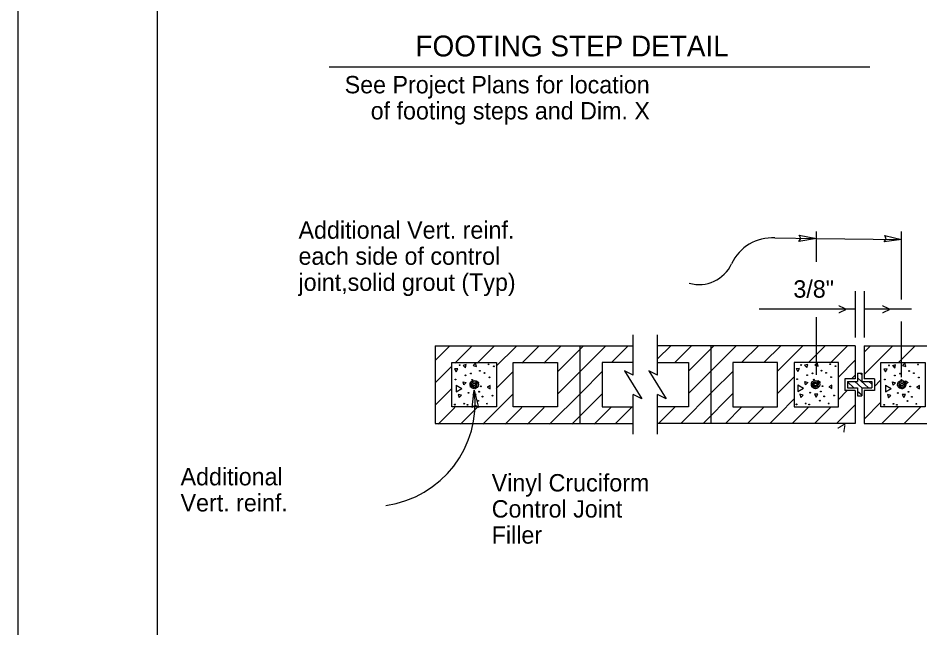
# Model space of a CAD drawing. Extents: x 0 to 2.83, y -0.03 to 1.83.
# Drawn here: x 0 to 0.675, y 0.861 to 1.317 of the extents above; entities that cross this region are included whole.
import ezdxf

# ---------------------------------------------------------------- set-up
doc = ezdxf.new("R2010")
doc.units = 0
for name, color, linetype in [('40', 7, 'Continuous'), ('50', 7, 'Continuous'), ('51', 7, 'Continuous'), ('52', 7, 'Continuous'), ('55', 7, 'Continuous'), ('57', 7, 'Continuous'), ('58', 7, 'Continuous'), ('63', 7, 'Continuous')]:
    doc.layers.add(name, color=color, linetype=linetype)

msp = doc.modelspace()

# ---------------------------------------------------------------- linework, layer by layer
at = {"layer": '40'}
for p, q in [((0.62848, 1.05162), (0.62848, 1.04547)), ((0.62848, 1.05162), (0.63155, 1.05162)), ((0.62848, 1.04833), (0.63661, 1.04084)), ((0.6303, 1.05162), (0.63155, 1.05046)), ((0.63155, 1.05162), (0.63155, 1.04547)), ((0.62095, 1.04547), (0.62095, 1.04084)), ((0.62095, 1.04547), (0.62848, 1.04547)), ((0.62095, 1.04514), (0.62563, 1.04084)), ((0.62095, 1.04084), (0.62848, 1.04084)), ((0.6263, 1.04547), (0.63155, 1.04064)), ((0.62848, 1.04084), (0.62848, 1.03469)), ((0.63155, 1.04547), (0.63908, 1.04547)), ((0.63155, 1.04084), (0.63155, 1.03469)), ((0.63155, 1.04084), (0.63908, 1.04084)), ((0.63699, 1.04547), (0.63908, 1.04355)), ((0.63908, 1.04547), (0.63908, 1.04084)), ((0.62848, 1.03822), (0.63155, 1.0354)), ((0.62848, 1.03469), (0.63155, 1.03469))]:
    msp.add_line(p, q, dxfattribs=at)
at = {"layer": '50'}
for p, q in [((0.59762, 1.13509), (0.59762, 1.15766)), ((0.66126, 1.10677), (0.66126, 1.15766)), ((0.59762, 1.05041), (0.59762, 1.09363)), ((0.66126, 1.04875), (0.66126, 1.09045)), ((0.31237, 1.07227), (0.31237, 1.01403)), ((0.31237, 1.07227), (0.46054, 1.07227)), ((0.42052, 1.07227), (0.42052, 1.01403)), ((0.62669, 1.07227), (0.4787, 1.07227)), ((0.51852, 1.07227), (0.51852, 1.01403)), ((0.62669, 1.07227), (0.62669, 1.0475)), ((0.63334, 1.07227), (0.7826, 1.07227)), ((0.63334, 1.07227), (0.63334, 1.0475)), ((0.61887, 1.0475), (0.61887, 1.03881)), ((0.62669, 1.0475), (0.61887, 1.0475)), ((0.64116, 1.0475), (0.63334, 1.0475)), ((0.64116, 1.0475), (0.64116, 1.03881)), ((0.62669, 1.03881), (0.61887, 1.03881)), ((0.62669, 1.03881), (0.62669, 1.01403)), ((0.64116, 1.03881), (0.63334, 1.03881)), ((0.63334, 1.03881), (0.63334, 1.01403)), ((0.31237, 1.01403), (0.46054, 1.01403)), ((0.62669, 1.01403), (0.4787, 1.01403)), ((0.63334, 1.01403), (0.7826, 1.01403))]:
    msp.add_line(p, q, dxfattribs=at)
for points in [[(0.32485, 1.02651), (0.32485, 1.0598), (0.35813, 1.0598), (0.35813, 1.02651)], [(0.37062, 1.02651), (0.37062, 1.0598), (0.4039, 1.0598), (0.4039, 1.02651)], [(0.56844, 1.02651), (0.56844, 1.0598), (0.53516, 1.0598), (0.53516, 1.02651)], [(0.61421, 1.02651), (0.61421, 1.0598), (0.58092, 1.0598), (0.58092, 1.02651)], [(0.64582, 1.02651), (0.64582, 1.0598), (0.67911, 1.0598), (0.67911, 1.02651)]]:
    msp.add_lwpolyline(points, close=True, dxfattribs=at)
for points in [[(0.46054, 1.0598), (0.43715, 1.0598), (0.43715, 1.02651), (0.46054, 1.02651)], [(0.4787, 1.0598), (0.50191, 1.0598), (0.50191, 1.02651), (0.4787, 1.02651)]]:
    msp.add_lwpolyline(points, dxfattribs=at)
for centre in [(0.33057, 1.05765), (0.34568, 1.05342), (0.35228, 1.05831), (0.35612, 1.05681), (0.58632, 1.0578), (0.60143, 1.05357), (0.60803, 1.05846), (0.61187, 1.05696), (0.65197, 1.05754), (0.66708, 1.05331), (0.67368, 1.0582), (0.32749, 1.04704), (0.33502, 1.05011), (0.33903, 1.05144), (0.33996, 1.04673), (0.34912, 1.05184), (0.35286, 1.04858), (0.58324, 1.04719), (0.59077, 1.05026), (0.59478, 1.05159), (0.59571, 1.04688), (0.60487, 1.05199), (0.60861, 1.04873), (0.64889, 1.04693), (0.65642, 1.05001), (0.66043, 1.05133), (0.66136, 1.04662), (0.67052, 1.05173), (0.67426, 1.04847), (0.33894, 1.04153), (0.34643, 1.04184), (0.59469, 1.04168), (0.60218, 1.04199), (0.66034, 1.04142), (0.66783, 1.04173), (0.33722, 1.037), (0.3452, 1.03783), (0.34775, 1.03418), (0.35511, 1.03488), (0.59297, 1.03715), (0.60095, 1.03798), (0.6035, 1.03433), (0.61086, 1.03503), (0.65862, 1.03689), (0.6666, 1.03772), (0.66915, 1.03407), (0.32705, 1.02819), (0.33388, 1.02889), (0.33643, 1.02806), (0.3444, 1.03101), (0.35105, 1.02889), (0.5828, 1.02834), (0.58963, 1.02904), (0.59218, 1.02821), (0.60015, 1.03116), (0.6068, 1.02904), (0.64845, 1.02808), (0.65528, 1.02878), (0.65783, 1.02795), (0.6658, 1.0309), (0.67245, 1.02878)]:
    msp.add_circle(centre, 0.000305, dxfattribs=at)
at = {"layer": '51'}
for p, q in [((0.32792, 1.04276), (0.32793, 1.0378)), ((0.32793, 1.04275), (0.33222, 1.04029)), ((0.32793, 1.0378), (0.33222, 1.04027)), ((0.34148, 1.04315), (0.34148, 1.04315)), ((0.34148, 1.04315), (0.34148, 1.04315)), ((0.58367, 1.04291), (0.58367, 1.03795)), ((0.58367, 1.0429), (0.58797, 1.04044)), ((0.58367, 1.03795), (0.58797, 1.04042)), ((0.59699, 1.0432), (0.59699, 1.0432)), ((0.59699, 1.0432), (0.59699, 1.0432)), ((0.64932, 1.04265), (0.64932, 1.03769)), ((0.64932, 1.04264), (0.65362, 1.04018)), ((0.64932, 1.03769), (0.65362, 1.04016)), ((0.66156, 1.04314), (0.66156, 1.04314)), ((0.66156, 1.04314), (0.66156, 1.04314))]:
    msp.add_line(p, q, dxfattribs=at)
for points in [[(0.34147, 1.04004), (0.3399, 1.04048), (0.33883, 1.04156), (0.3384, 1.04278), (0.33857, 1.04427), (0.33925, 1.04535), (0.34027, 1.04602), (0.34155, 1.04626), (0.34283, 1.04597), (0.34378, 1.04527), (0.34437, 1.04436), (0.34462, 1.04318), (0.34437, 1.04196), (0.3438, 1.04109), (0.34295, 1.04039), (0.34213, 1.0401), (0.34158, 1.04003), (0.34112, 1.0411), (0.34018, 1.04153), (0.33952, 1.04254), (0.33952, 1.04375), (0.3401, 1.04472), (0.34118, 1.04522), (0.34258, 1.04492), (0.3433, 1.04418), (0.34357, 1.04311), (0.34328, 1.04211), (0.34268, 1.04145), (0.34187, 1.04109), (0.34115, 1.04109), (0.34088, 1.04231), (0.3405, 1.04286), (0.34055, 1.04357), (0.34107, 1.04408), (0.34195, 1.04407), (0.34245, 1.04353), (0.34243, 1.04277), (0.3419, 1.04221), (0.34125, 1.04214), (0.34088, 1.04228)], [(0.59697, 1.04008), (0.59539, 1.04052), (0.59432, 1.0416), (0.59389, 1.04282), (0.59407, 1.04431), (0.59476, 1.04539), (0.59576, 1.04606), (0.59706, 1.0463), (0.59832, 1.04601), (0.59927, 1.04531), (0.59986, 1.0444), (0.60011, 1.04322), (0.59987, 1.042), (0.59929, 1.04113), (0.59844, 1.04043), (0.59762, 1.04015), (0.59707, 1.04007), (0.59662, 1.04115), (0.59569, 1.04157), (0.59501, 1.04258), (0.59501, 1.0438), (0.59561, 1.04476), (0.59667, 1.04526), (0.59807, 1.04496), (0.59881, 1.04422), (0.59906, 1.04315), (0.59879, 1.04215), (0.59817, 1.04149), (0.59737, 1.04113), (0.59664, 1.04113), (0.59639, 1.04235), (0.59601, 1.0429), (0.59606, 1.04361), (0.59656, 1.04412), (0.59744, 1.04411), (0.59796, 1.04357), (0.59794, 1.04281), (0.59741, 1.04225), (0.59676, 1.04218), (0.59639, 1.04232)], [(0.66154, 1.04002), (0.65996, 1.04046), (0.65889, 1.04155), (0.65846, 1.04276), (0.65864, 1.04425), (0.65932, 1.04533), (0.66032, 1.046), (0.66162, 1.04625), (0.66289, 1.04595), (0.66384, 1.04525), (0.66442, 1.04435), (0.66467, 1.04316), (0.66444, 1.04195), (0.66386, 1.04107), (0.66301, 1.04037), (0.66219, 1.04009), (0.66164, 1.04001), (0.66119, 1.04109), (0.66026, 1.04151), (0.65957, 1.04252), (0.65957, 1.04374), (0.66017, 1.0447), (0.66124, 1.0452), (0.66264, 1.0449), (0.66337, 1.04416), (0.66362, 1.0431), (0.66336, 1.0421), (0.66274, 1.04143), (0.66194, 1.04107), (0.66121, 1.04107), (0.66096, 1.0423), (0.66057, 1.04285), (0.66062, 1.04355), (0.66112, 1.04406), (0.66201, 1.04405), (0.66252, 1.04351), (0.66251, 1.04275), (0.66197, 1.0422), (0.66132, 1.04212), (0.66096, 1.04226)]]:
    msp.add_lwpolyline(points, dxfattribs=at)
at = {"layer": '52'}
for p, q in [((0.32677, 1.05494), (0.32802, 1.05279)), ((0.32925, 1.05495), (0.32678, 1.05493)), ((0.32802, 1.05279), (0.32925, 1.05494)), ((0.33548, 1.05809), (0.3331, 1.05743)), ((0.3331, 1.05744), (0.33485, 1.05568)), ((0.33485, 1.05568), (0.3355, 1.05808)), ((0.34068, 1.05745), (0.34308, 1.0568)), ((0.34243, 1.0592), (0.3407, 1.05745)), ((0.34308, 1.0568), (0.34245, 1.0592)), ((0.58499, 1.0551), (0.58252, 1.05508)), ((0.58252, 1.05509), (0.58376, 1.05294)), ((0.58376, 1.05294), (0.58501, 1.05509)), ((0.59124, 1.05824), (0.58884, 1.05758)), ((0.58884, 1.05759), (0.59059, 1.05583)), ((0.59059, 1.05583), (0.59124, 1.05823)), ((0.59644, 1.0576), (0.59884, 1.05695)), ((0.59817, 1.05935), (0.59646, 1.0576)), ((0.59884, 1.05695), (0.59819, 1.05935)), ((0.65064, 1.05484), (0.64817, 1.05482)), ((0.64817, 1.05483), (0.64941, 1.05268)), ((0.64941, 1.05268), (0.65066, 1.05483)), ((0.65689, 1.05798), (0.65449, 1.05732)), ((0.65449, 1.05733), (0.65624, 1.05557)), ((0.65624, 1.05557), (0.65689, 1.05797)), ((0.66209, 1.05734), (0.66449, 1.05669)), ((0.66382, 1.0591), (0.66211, 1.05734)), ((0.66449, 1.05669), (0.66384, 1.05909)), ((0.33377, 1.04287), (0.33313, 1.04526)), ((0.33313, 1.04525), (0.33553, 1.04463)), ((0.33553, 1.04462), (0.33377, 1.04287)), ((0.34288, 1.0436), (0.34288, 1.04608)), ((0.34288, 1.04607), (0.34503, 1.04485)), ((0.34503, 1.04484), (0.34288, 1.0436)), ((0.35127, 1.04135), (0.35342, 1.0401)), ((0.3534, 1.0426), (0.35128, 1.04135)), ((0.35342, 1.0401), (0.35342, 1.04259)), ((0.58952, 1.04302), (0.58887, 1.04541)), ((0.58889, 1.0454), (0.59127, 1.04478)), ((0.59127, 1.04477), (0.58952, 1.04302)), ((0.59864, 1.04375), (0.59864, 1.04623)), ((0.59864, 1.04622), (0.60079, 1.045)), ((0.60079, 1.04499), (0.59864, 1.04375)), ((0.60701, 1.0415), (0.60916, 1.04025)), ((0.60914, 1.04275), (0.60702, 1.0415)), ((0.60916, 1.04025), (0.60916, 1.04274)), ((0.65517, 1.04276), (0.65452, 1.04515)), ((0.65454, 1.04515), (0.65692, 1.04452)), ((0.65692, 1.04451), (0.65517, 1.04276)), ((0.66429, 1.04349), (0.66429, 1.04597)), ((0.66429, 1.04596), (0.66644, 1.04474)), ((0.66644, 1.04473), (0.66429, 1.04349)), ((0.67266, 1.04125), (0.67481, 1.04)), ((0.67479, 1.04249), (0.67267, 1.04124)), ((0.67481, 1.04), (0.67481, 1.04248)), ((0.32957, 1.03578), (0.33022, 1.03338)), ((0.33197, 1.03515), (0.32957, 1.03577)), ((0.33022, 1.03338), (0.33197, 1.03514)), ((0.34298, 1.03575), (0.3405, 1.03574)), ((0.3405, 1.03575), (0.34173, 1.0336)), ((0.34173, 1.0336), (0.34298, 1.03575)), ((0.58531, 1.03593), (0.58596, 1.03353)), ((0.58771, 1.0353), (0.58532, 1.03592)), ((0.58596, 1.03353), (0.58771, 1.03529)), ((0.59872, 1.0359), (0.59624, 1.03589)), ((0.59624, 1.0359), (0.59749, 1.03375)), ((0.59749, 1.03375), (0.59872, 1.0359)), ((0.65096, 1.03567), (0.65161, 1.03327)), ((0.65336, 1.03504), (0.65097, 1.03566)), ((0.65161, 1.03327), (0.65336, 1.03503)), ((0.66437, 1.03565), (0.66189, 1.03563)), ((0.66189, 1.03564), (0.66314, 1.03349)), ((0.66314, 1.03349), (0.66437, 1.03564))]:
    msp.add_line(p, q, dxfattribs=at)
at = {"layer": '55'}
for p, q in [((0.56658, 1.15287), (0.59759, 1.15239)), ((0.59759, 1.15239), (0.66145, 1.15175)), ((0.62669, 1.11301), (0.62669, 1.07838)), ((0.63334, 1.11301), (0.63334, 1.07838)), ((0.62669, 1.09969), (0.55475, 1.09969)), ((0.66886, 1.09969), (0.63334, 1.09969)), ((0.46054, 1.05013), (0.46054, 1.08049)), ((0.4787, 1.05013), (0.4787, 1.08049)), ((0.45403, 1.05339), (0.46705, 1.03239)), ((0.46054, 1.05013), (0.45403, 1.05339)), ((0.47218, 1.05339), (0.48521, 1.03239)), ((0.4787, 1.05013), (0.47218, 1.05339)), ((0.46054, 1.00618), (0.46054, 1.03565)), ((0.46705, 1.03239), (0.46054, 1.03565)), ((0.4787, 1.00618), (0.4787, 1.03565)), ((0.48521, 1.03239), (0.4787, 1.03565))]:
    msp.add_line(p, q, dxfattribs=at)
for points in [[(0.59759, 1.15239), (0.58457, 1.15018), (0.58611, 1.15253), (0.58478, 1.15495)], [(0.66145, 1.15175), (0.64836, 1.15004), (0.64998, 1.15234), (0.64875, 1.1548)], [(0.34157, 1.03894), (0.34477, 1.02612), (0.34231, 1.02748), (0.33999, 1.02597)]]:
    msp.add_lwpolyline(points, close=True, dxfattribs=at)
for centre, radius, start, end in [((0.56448, 1.11949), 0.03344, 86.39375, 155.06774), ((0.50982, 1.14481), 0.02679, 254.16193, 335.24743), ((0.26488, 1.02932), 0.07729, 277.72953, 7.14746)]:
    msp.add_arc(centre, radius, start, end, dxfattribs=at)
at = {"layer": '57'}
msp.add_line((0.23291, 1.28093), (0.63775, 1.28093), dxfattribs=at)
at = {"layer": '58'}
for p, q in [((0.42177, 1.07067), (0.40377, 1.05267)), ((0.4886, 1.07227), (0.4787, 1.06237)), ((0.50425, 1.07227), (0.49178, 1.0598)), ((0.53758, 1.07227), (0.50191, 1.0366)), ((0.52092, 1.07227), (0.50191, 1.05325)), ((0.55425, 1.07227), (0.54191, 1.05992)), ((0.57091, 1.07227), (0.55857, 1.05992)), ((0.58758, 1.07227), (0.56844, 1.05313)), ((0.60426, 1.07227), (0.59191, 1.05992)), ((0.62091, 1.07227), (0.60857, 1.05992)), ((0.67156, 1.07227), (0.65909, 1.0598)), ((0.42177, 1.054), (0.4051, 1.03734)), ((0.58079, 1.04881), (0.56844, 1.03646)), ((0.62669, 1.0503), (0.62389, 1.0475)), ((0.32472, 1.04029), (0.32177, 1.03734)), ((0.64571, 1.04641), (0.64116, 1.04186)), ((0.43702, 1.03592), (0.42177, 1.02067)), ((0.62079, 1.03881), (0.61407, 1.0321)), ((0.49185, 1.02651), (0.47937, 1.01403)), ((0.54183, 1.02651), (0.52947, 1.01415)), ((0.5585, 1.02651), (0.54614, 1.01415)), ((0.58079, 1.03215), (0.56996, 1.02131)), ((0.65912, 1.02651), (0.64666, 1.01403)), ((0.67581, 1.02651), (0.66332, 1.01403)), ((0.34377, 1.026), (0.33843, 1.02067))]:
    msp.add_line(p, q, dxfattribs=at)
for points in [[(0.32285, 1.07175), (0.31223, 1.06114)], [(0.33843, 1.07067), (0.32705, 1.05928)], [(0.33952, 1.07175), (0.33843, 1.07067)], [(0.35618, 1.07175), (0.34372, 1.05928)], [(0.37285, 1.07175), (0.358, 1.0569)], [(0.38952, 1.07175), (0.37705, 1.05928)], [(0.40618, 1.07175), (0.39372, 1.05928)], [(0.43952, 1.07175), (0.42177, 1.054)], [(0.42285, 1.07175), (0.42177, 1.07067)], [(0.4567, 1.07227), (0.44423, 1.0598)], [(0.65489, 1.07227), (0.63334, 1.05072)], [(0.63822, 1.07227), (0.63334, 1.06739)], [(0.62669, 1.06137), (0.61407, 1.04876)], [(0.32472, 1.05695), (0.31223, 1.04447)], [(0.37048, 1.05272), (0.358, 1.04024)], [(0.43702, 1.05259), (0.42177, 1.03734)], [(0.53502, 1.05305), (0.51996, 1.03798)], [(0.32177, 1.03734), (0.31223, 1.0278)], [(0.37048, 1.03605), (0.34795, 1.01351)], [(0.42177, 1.03734), (0.39795, 1.01351)], [(0.4051, 1.03734), (0.40377, 1.036)], [(0.51996, 1.03798), (0.49614, 1.01415)], [(0.53502, 1.03638), (0.51281, 1.01415)], [(0.45978, 1.02651), (0.4473, 1.01403)], [(0.59196, 1.02664), (0.57947, 1.01415)], [(0.60862, 1.02664), (0.59614, 1.01415)], [(0.62669, 1.02804), (0.61281, 1.01415)], [(0.64571, 1.02975), (0.63334, 1.01739)], [(0.3271, 1.026), (0.31462, 1.01351)], [(0.33843, 1.02067), (0.33128, 1.01351)], [(0.3771, 1.026), (0.36462, 1.01351)], [(0.39377, 1.026), (0.38128, 1.01351)], [(0.42177, 1.02067), (0.41462, 1.01351)], [(0.44377, 1.026), (0.43128, 1.01351)], [(0.56996, 1.02131), (0.56281, 1.01415)]]:
    msp.add_lwpolyline(points, dxfattribs=at)
at = {"layer": '63'}
msp.add_line((0, 0), (0, 1.83333), dxfattribs=at)
msp.add_lwpolyline([(2.72918, 1.77077), (0.10418, 1.77077), (0.10418, 0.06244), (2.72918, 0.06244)], close=True, dxfattribs=at)

# ---------------------------------------------------------------- texts
at = {"layer": '55'}
for p in [(0.61367, 1.09535), (0.64636, 1.09535)]:
    msp.add_text('>', height=0.00868, dxfattribs=at).set_placement(p)
msp.add_text('>', height=0.00867, rotation=56.61658, dxfattribs=at).set_placement((0.61901, 1.00614))
msp.add_text('>', height=0.00867, rotation=56.61658, dxfattribs=at).set_placement((0.61901, 1.00614))
at = {"layer": '57'}
for s, height, p in [('FOOTING STEP DETAIL', 0.015625, (0.29751, 1.28874)), ('See Project Plans for location ', 0.0130167, (0.24451, 1.26111)), ('of footing steps and Dim. X', 0.0130167, (0.26399, 1.24158)), ('Additional Vert. reinf.', 0.0130167, (0.20997, 1.15234)), ('each side of control', 0.0130167, (0.20997, 1.13282)), ('joint,solid grout (Typ)', 0.0130167, (0.20997, 1.11329)), ('3/8" ', 0.013017, (0.58042, 1.10821)), ('Additional', 0.013017, (0.12167, 0.96776)), ('Vinyl Cruciform ', 0.0130167, (0.3546, 0.96318)), ('Vert. reinf.', 0.0130167, (0.12167, 0.94823)), ('Control Joint ', 0.0130167, (0.3546, 0.94365)), ('Filler', 0.013017, (0.3546, 0.92414))]:
    msp.add_text(s, height=height, dxfattribs=at).set_placement(p)

doc.saveas('drawing.dxf')
